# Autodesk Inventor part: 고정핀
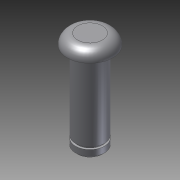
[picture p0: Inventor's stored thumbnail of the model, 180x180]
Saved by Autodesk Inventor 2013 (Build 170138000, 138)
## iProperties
Created: 2010-03
Part Number: 고정핀
Document SubType Name: Modeling
Designer: Administrator
Density: 1 g/cm^3
Material: 강철, 연강
Author: Administrator
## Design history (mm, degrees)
sketch "스케치1"
  geometry: L1 (16.577, 14.126)-(28.417, -20.867) reference; L2 (-28.417, -20.867)-(-16.577, 14.126) reference; C1 r 18.5 at (0, -30.483) reference; C2 r 7 at (0, 8.517) reference; A1 r 17.5 centre (0, 8.517) between (16.577, 14.126) and (-16.577, 14.126) reference; A2 r 30 centre (0, -30.483) between (-28.417, -20.867) and (28.417, -20.867) reference
extrude "돌출1" new body sketch "스케치1" distance "d0" = 43; taper "d1" = 0 deg
sketch "스케치2"
  geometry: C1 r 7 at (0, 0) reference; C2 r 11 at (0, 0); 1 further point
  constraints: 1 centre point, 1 coincident
  dimensions: "d2" = 22 diameter of C2
extrude "돌출2" join sketch "스케치2" distance "d3" = 5; taper "d4" = 0 deg
fillet "모깎기1" dims "d5" = 5
sketch "스케치4"
  geometry: L1 (-20.867, -38)-(14.126, -38) reference; L2 (15.517, -43)-(1.517, -43) reference; L3 (8.517, -43)-(8.517, -38); L4 (1.517, 0)-(1.517, -43) reference; L5 (1.517, -38)-(2.517, -38); L6 (2.517, -38)-(2.517, -39.15); L7 (2.517, -39.15)-(1.517, -39.15); L8 (1.517, -39.15)-(1.517, -38); 1 further point
  constraints: 12 end point, 3 point on line, 2 horizontal, 2 parallel, 2 perpendicular, 1 midpoint, 2 other
  dimensions: "d10" = 12 diameter of L6 L3; "d13" = 1.15 distance between parallel lines of L7 L1
revolve "회전1" sketch "스케치4" stored, may be unused: angle "d14" = 90 deg
chamfer "모따기1" distance "d15" = 1; stored, may be unused: second distance "d16" = 2, angle "d17" = 45 deg
node "솔리드1"
node "참조1"
